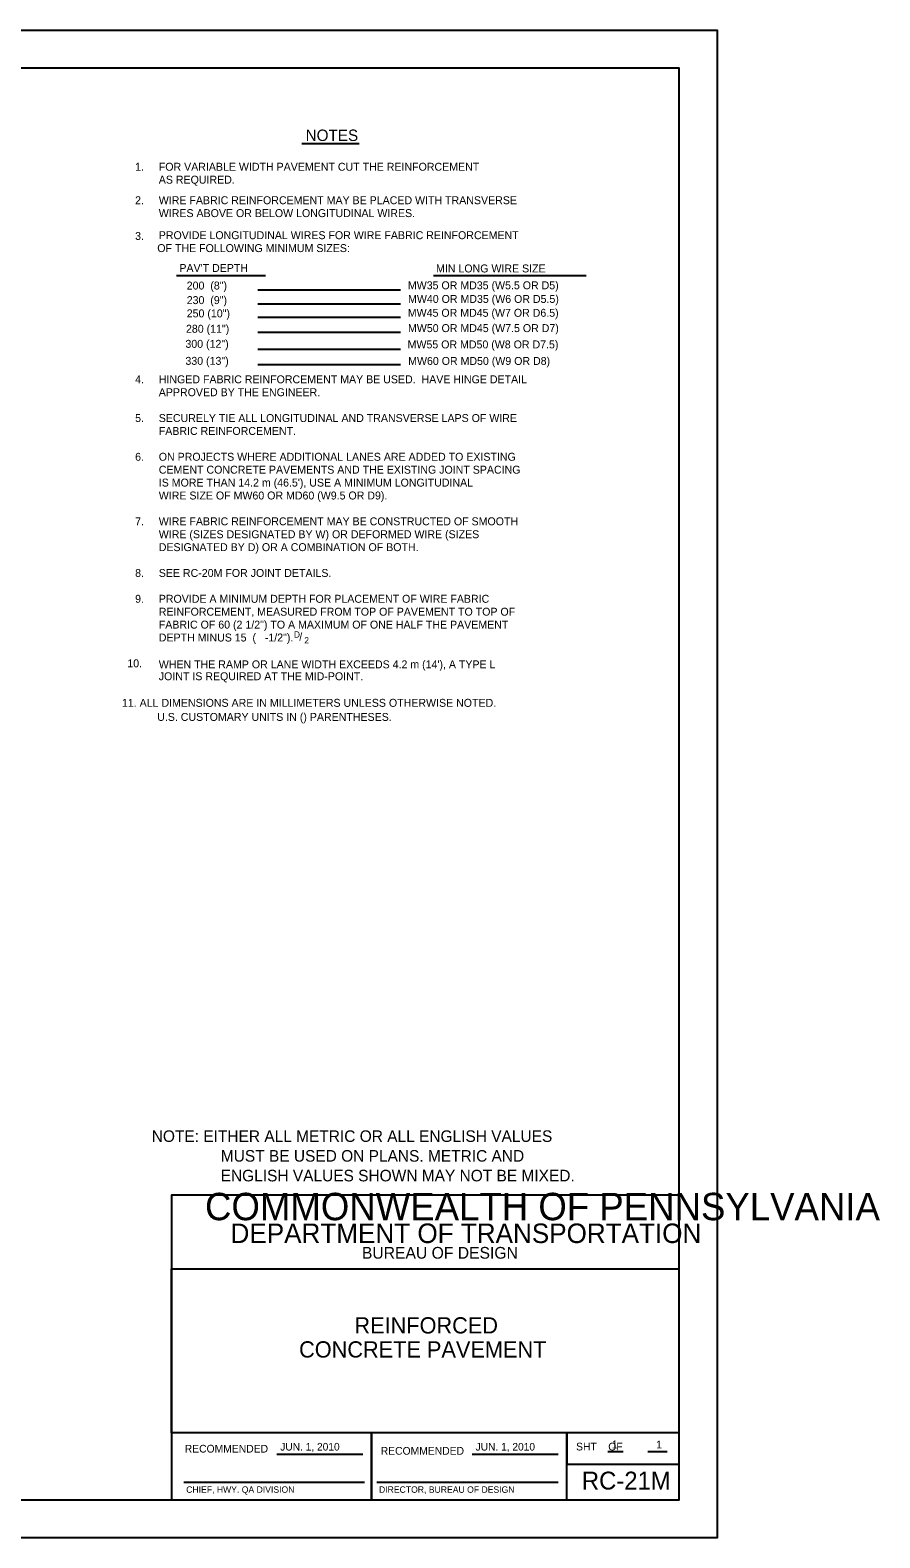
# Model space of a CAD drawing. Extents: x 638703 to 639608, y 298343 to 298937.
# Drawn here: x 639273 to 639608, y 298343 to 298937 of the extents above; entities that cross this region are included whole.
import ezdxf

# ---------------------------------------------------------------- set-up
doc = ezdxf.new("R2010")
doc.units = 0
for name, color, linetype in [('1', 7, 'Continuous'), ('2', 7, 'Continuous'), ('3', 7, 'Continuous'), ('40', 7, 'Continuous'), ('PLT-BNDY', 7, 'Continuous')]:
    doc.layers.add(name, color=color, linetype=linetype)

msp = doc.modelspace()

# ---------------------------------------------------------------- linework, layer by layer
at = {"layer": '1'}
for p, q in [((639370.401, 298375.627375), (639404.2875, 298375.627375)), ((639447.399, 298375.627375), (639481.269, 298375.627375)), ((639500.8015, 298376.611375), (639506.9435, 298376.611375)), ((639516.611, 298376.611375), (639524.2575, 298376.611375)), ((639333.698, 298364.63925), (639404.9475, 298364.63925)), ((639409.8675, 298364.63925), (639481.2075, 298364.63925))]:
    msp.add_line(p, q, dxfattribs=at)
msp.add_lwpolyline([(639528.936, 298357.638375), (639528.936, 298921.638375), (638742.936, 298921.638375), (638742.936, 298357.638375), (639528.936, 298357.638375), (639528.936, 298383.997375), (639328.936, 298383.997375), (639328.936, 298448.674875), (639528.936, 298448.674875), (639528.936, 298477.638375), (639328.936, 298477.638375), (639328.936, 298357.638375), (639407.7375, 298357.638375), (639407.7375, 298383.997375), (639407.7375, 298357.638375), (639484.7375, 298357.638375), (639484.7375, 298383.997375), (639484.7375, 298371.680875), (639528.936, 298371.680875)], dxfattribs=at)
at = {"layer": '2'}
for p, q in [((639380.285, 298891.998375), (639402.85875, 298891.998375)), ((639330.8405, 298839.915125), (639365.94575, 298839.915125)), ((639432.0925, 298839.989125), (639492.32475, 298839.989125)), ((639362.93775, 298834.327375), (639419.194, 298834.327375)), ((639362.93775, 298828.783875), (639419.194, 298828.783875)), ((639362.93775, 298823.615875), (639419.194, 298823.615875)), ((639362.93775, 298817.634125), (639419.194, 298817.634125)), ((639362.93775, 298810.976625), (639419.194, 298810.976625)), ((639362.93775, 298804.885625), (639419.194, 298804.885625))]:
    msp.add_line(p, q, dxfattribs=at)
at = {"layer": 'PLT-BNDY'}
msp.add_lwpolyline([(638702.936, 298936.638375), (639543.936, 298936.638375), (639543.936, 298342.638375), (638702.936, 298342.638375)], close=True, dxfattribs=at)

# ---------------------------------------------------------------- texts
at = {"layer": '1'}
for s, height, p in [('COMMONWEALTH OF PENNSYLVANIA', 10.7833725, (639342.087, 298467.781875)), ('DEPARTMENT OF TRANSPORTATION', 7.6842885, (639352.148, 298458.787625)), ('BUREAU OF DESIGN', 4.6220925, (639403.9225, 298452.625375)), ('REINFORCED', 6.4000005, (639400.97475, 298423.151375)), ('CONCRETE PAVEMENT', 6.4000005, (639379.15875, 298413.678375)), ('RECOMMENDED', 3.048, (639334.0995, 298376.231875)), ('JUN. 1, 2010', 3, (639371.739526, 298377.029981)), ('RECOMMENDED', 3.048, (639411.3435, 298375.395625)), ('JUN. 1, 2010', 3, (639448.737526, 298377.029981)), ('SHT    OF', 3.048, (639488.3415, 298377.068375)), ('1', 3.124999, (639502.42075, 298377.866875)), ('1', 3.124999, (639519.8815, 298377.842125)), ('RC-21M', 7.0332495, (639490.616, 298361.681875)), ('CHIEF, HWY. QA DIVISION', 2.5399995, (639334.673948, 298360.38125)), ('DIRECTOR, BUREAU OF DESIGN', 2.5399995, (639410.661333, 298360.38125))]:
    msp.add_text(s, height=height, dxfattribs=at).set_placement(p)
at = {"layer": '2'}
for s, p in [(' 11. ALL DIMENSIONS ARE IN MILLIMETERS UNLESS OTHERWISE NOTED.', (639308.17925, 298670.048375)), ('U.S. CUSTOMARY UNITS IN () PARENTHESES.', (639323.24625, 298664.501875))]:
    msp.add_text(s, height=3.126, dxfattribs=at).set_placement(p)
at = {"layer": '3'}
for s, height, p in [('NOTES', 4.5, (639381.72675, 298892.969125)), ('1.  ', 3.1249995, (639314.545223, 298881.258875)), ('FOR VARIABLE WIDTH PAVEMENT CUT THE REINFORCEMENT ', 3.1249995, (639323.86625, 298881.258875)), ('AS REQUIRED.', 3.1249995, (639323.86625, 298876.173375)), ('2.  ', 3.1249995, (639314.545223, 298868.071375)), ('WIRE FABRIC REINFORCEMENT MAY BE PLACED WITH TRANSVERSE', 3.1249995, (639323.86625, 298868.071375)), ('WIRES ABOVE OR BELOW LONGITUDINAL WIRES.', 3.1249995, (639323.86625, 298862.986125)), ('3.  ', 3.1249995, (639314.545223, 298853.996625)), ('PROVIDE LONGITUDINAL WIRES FOR WIRE FABRIC REINFORCEMENT ', 3.1249995, (639323.86625, 298854.292375)), ('OF THE FOLLOWING MINIMUM SIZES:', 3.1249995, (639323.2745, 298849.205125)), ("PAV'T DEPTH", 3.1249995, (639331.9925, 298841.375875)), ('MIN LONG WIRE SIZE', 3.1249995, (639433.1465, 298841.186125)), ('200  (8")', 3.1249995, (639334.87925, 298834.456875)), ('MW35 OR MD35 (W5.5 OR D5)', 3.1249995, (639422.04125, 298834.549125)), ('230  (9")', 3.1249995, (639334.87925, 298828.712875)), ('MW40 OR MD35 (W6 OR D5.5)', 3.1249995, (639422.1085, 298829.178875)), ('250 (10")', 3.1249995, (639334.88, 298823.487875)), ('MW45 OR MD45 (W7 OR D6.5)', 3.1249995, (639422.01575, 298823.712375)), ('280 (11")', 3.1249995, (639334.584, 298817.430875)), ('MW50 OR MD45 (W7.5 OR D7)', 3.1249995, (639422.08225, 298817.680375)), ('300 (12")', 3.1249995, (639334.3645, 298811.487875)), ('MW55 OR MD50 (W8 OR D7.5)', 3.1249995, (639421.93775, 298811.259875)), ('330 (13")', 3.1249995, (639334.36475, 298804.788875)), ('MW60 OR MD50 (W9 OR D8)', 3.1249995, (639422.14275, 298804.747375)), ('4.  ', 3.1249995, (639314.545223, 298797.510375)), ('HINGED FABRIC REINFORCEMENT MAY BE USED.  HAVE HINGE DETAIL', 3.1249995, (639323.86625, 298797.510375)), ('APPROVED BY THE ENGINEER.', 3.1249995, (639323.86625, 298792.424875)), ('5.  ', 3.1249995, (639314.545223, 298782.251875)), ('SECURELY TIE ALL LONGITUDINAL AND TRANSVERSE LAPS OF WIRE', 3.1249995, (639323.86625, 298782.251875)), ('FABRIC REINFORCEMENT.', 3.1249995, (639323.86625, 298777.164375)), ('6.  ', 3.1249995, (639314.545223, 298766.993625)), ('ON PROJECTS WHERE ADDITIONAL LANES ARE ADDED TO EXISTING', 3.1249995, (639323.86625, 298766.993625)), ('CEMENT CONCRETE PAVEMENTS AND THE EXISTING JOINT SPACING', 3.1249995, (639323.86625, 298761.908125)), ("IS MORE THAN 14.2 m (46.5'), USE A MINIMUM LONGITUDINAL", 3.1249995, (639323.86625, 298756.820625)), ('WIRE SIZE OF MW60 OR MD60 (W9.5 OR D9).', 3.1249995, (639323.86625, 298751.735375)), ('7.  ', 3.1249995, (639314.545223, 298741.562375)), ('WIRE FABRIC REINFORCEMENT MAY BE CONSTRUCTED OF SMOOTH ', 3.1249995, (639323.86625, 298741.562375)), ('WIRE (SIZES DESIGNATED BY W) OR DEFORMED WIRE (SIZES ', 3.1249995, (639323.86625, 298736.474875)), ('DESIGNATED BY D) OR A COMBINATION OF BOTH.', 3.1249995, (639323.86625, 298731.389375)), ('8.  ', 3.1249995, (639314.545223, 298721.216625)), ('SEE RC-20M FOR JOINT DETAILS.', 3.1249995, (639323.86625, 298721.216625)), ('9.  ', 3.1249995, (639314.545223, 298711.043625)), ('PROVIDE A MINIMUM DEPTH FOR PLACEMENT OF WIRE FABRIC', 3.1249995, (639323.86625, 298711.043625)), ('REINFORCEMENT, MEASURED FROM TOP OF PAVEMENT TO TOP OF', 3.1249995, (639323.86625, 298705.956125)), ('FABRIC OF 60 (2 1/2") TO A MAXIMUM OF ONE HALF THE PAVEMENT', 3.1249995, (639323.86625, 298700.870625)), ('DEPTH MINUS 15  (   -1/2").', 3.1249995, (639323.86625, 298695.785375)), ('D', 2.5, (639377.106346, 298697.285611)), ('/', 3.124999, (639379.261119, 298696.131549)), ('2', 2.5, (639381.204743, 298695.011211)), ('10. ', 3.1249995, (639311.46425, 298685.612375)), ("WHEN THE RAMP OR LANE WIDTH EXCEEDS 4.2 m (14'), A TYPE L", 3.1249995, (639323.86625, 298685.212375)), ('JOINT IS REQUIRED AT THE MID-POINT.', 3.1249995, (639323.86625, 298680.524875))]:
    msp.add_text(s, height=height, dxfattribs=at).set_placement(p)
at = {"layer": '40'}
for s, p in [('NOTE: EITHER ALL METRIC OR ALL ENGLISH VALUES', (639321.09125, 298498.618625)), ('MUST BE USED ON PLANS. METRIC AND', (639348.316, 298490.850625)), ('ENGLISH VALUES SHOWN MAY NOT BE MIXED.', (639348.2435, 298483.082375))]:
    msp.add_text(s, height=4.558749, dxfattribs=at).set_placement(p)

doc.saveas('drawing.dxf')
